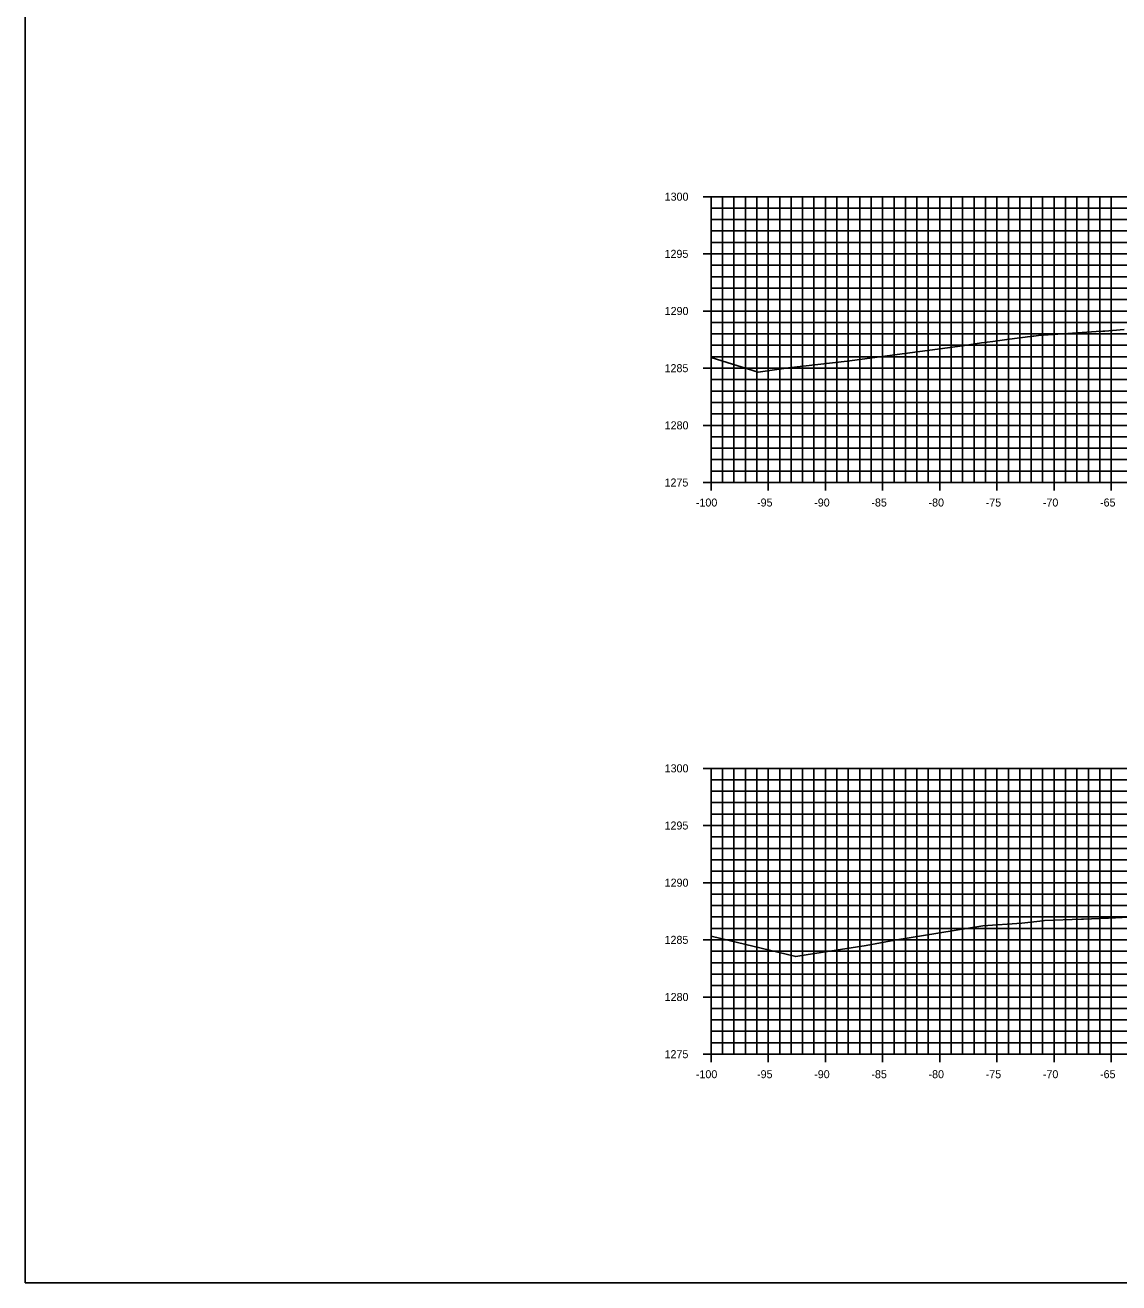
# Model space of a CAD drawing. Extents: x 674939 to 678919, y 750652 to 765176.
# Drawn here: x 677778.5 to 677874.2, y 757592.6 to 757702.6 of the extents above; entities that cross this region are included whole.
import ezdxf

# ---------------------------------------------------------------- set-up
doc = ezdxf.new("R2010")
doc.units = 0
for name, color, linetype in [('R_Axis', 7, 'Continuous'), ('R_Axis Annot', 7, 'Continuous'), ('R_Exist Surface', 7, 'Continuous'), ('R_Grid', 7, 'Continuous'), ('R_No Plot', 7, 'Continuous')]:
    doc.layers.add(name, color=color, linetype=linetype)

msp = doc.modelspace()

# ---------------------------------------------------------------- linework, layer by layer
at = {"layer": 'R_Axis'}
for p, q in [((677837.83, 757687.55), (677839.23, 757687.55)), ((677838.53, 757662.55), (677838.53, 757687.55)), ((677838.53, 757686.55), (677838.88, 757686.55)), ((677838.53, 757685.55), (677838.88, 757685.55)), ((677838.53, 757684.55), (677838.88, 757684.55)), ((677838.53, 757683.55), (677838.88, 757683.55)), ((677837.83, 757682.55), (677839.23, 757682.55)), ((677838.53, 757681.55), (677838.88, 757681.55)), ((677838.53, 757680.55), (677838.88, 757680.55)), ((677838.53, 757679.55), (677838.88, 757679.55)), ((677838.53, 757678.55), (677838.88, 757678.55)), ((677837.83, 757677.55), (677839.23, 757677.55)), ((677838.53, 757676.55), (677838.88, 757676.55)), ((677838.53, 757675.55), (677838.88, 757675.55)), ((677838.53, 757674.55), (677838.88, 757674.55)), ((677838.53, 757673.55), (677838.88, 757673.55)), ((677837.83, 757672.55), (677839.23, 757672.55)), ((677838.53, 757671.55), (677838.88, 757671.55)), ((677838.53, 757670.55), (677838.88, 757670.55)), ((677838.53, 757669.55), (677838.88, 757669.55)), ((677838.53, 757668.55), (677838.88, 757668.55)), ((677837.83, 757667.55), (677839.23, 757667.55)), ((677838.53, 757666.55), (677838.88, 757666.55)), ((677838.53, 757665.55), (677838.88, 757665.55)), ((677838.53, 757664.55), (677838.88, 757664.55)), ((677838.53, 757663.55), (677838.88, 757663.55)), ((677837.83, 757662.55), (677839.23, 757662.55)), ((677838.53, 757661.85), (677838.53, 757663.25)), ((677838.53, 757662.55), (678038.53, 757662.55)), ((677843.53, 757661.85), (677843.53, 757663.25)), ((677848.53, 757661.85), (677848.53, 757663.25)), ((677853.53, 757661.85), (677853.53, 757663.25)), ((677858.53, 757661.85), (677858.53, 757663.25)), ((677863.53, 757661.85), (677863.53, 757663.25)), ((677868.53, 757661.85), (677868.53, 757663.25)), ((677873.53, 757661.85), (677873.53, 757663.25)), ((677837.83, 757637.55), (677839.23, 757637.55)), ((677838.53, 757612.55), (677838.53, 757637.55)), ((677838.53, 757636.55), (677838.88, 757636.55)), ((677838.53, 757635.55), (677838.88, 757635.55)), ((677838.53, 757634.55), (677838.88, 757634.55)), ((677838.53, 757633.55), (677838.88, 757633.55)), ((677837.83, 757632.55), (677839.23, 757632.55)), ((677838.53, 757631.55), (677838.88, 757631.55)), ((677838.53, 757630.55), (677838.88, 757630.55)), ((677838.53, 757629.55), (677838.88, 757629.55)), ((677838.53, 757628.55), (677838.88, 757628.55)), ((677837.83, 757627.55), (677839.23, 757627.55)), ((677838.53, 757626.55), (677838.88, 757626.55)), ((677838.53, 757625.55), (677838.88, 757625.55)), ((677838.53, 757624.55), (677838.88, 757624.55)), ((677838.53, 757623.55), (677838.88, 757623.55)), ((677837.83, 757622.55), (677839.23, 757622.55)), ((677838.53, 757621.55), (677838.88, 757621.55)), ((677838.53, 757620.55), (677838.88, 757620.55)), ((677838.53, 757619.55), (677838.88, 757619.55)), ((677838.53, 757618.55), (677838.88, 757618.55)), ((677837.83, 757617.55), (677839.23, 757617.55)), ((677838.53, 757616.55), (677838.88, 757616.55)), ((677838.53, 757615.55), (677838.88, 757615.55)), ((677838.53, 757614.55), (677838.88, 757614.55)), ((677838.53, 757613.55), (677838.88, 757613.55)), ((677838.53, 757611.85), (677838.53, 757613.25)), ((677843.53, 757611.85), (677843.53, 757613.25)), ((677848.53, 757611.85), (677848.53, 757613.25)), ((677853.53, 757611.85), (677853.53, 757613.25)), ((677858.53, 757611.85), (677858.53, 757613.25)), ((677863.53, 757611.85), (677863.53, 757613.25)), ((677868.53, 757611.85), (677868.53, 757613.25)), ((677873.53, 757611.85), (677873.53, 757613.25)), ((677837.83, 757612.55), (677839.23, 757612.55)), ((677838.53, 757612.55), (678038.53, 757612.55))]:
    msp.add_line(p, q, dxfattribs=at)
at = {"layer": 'R_Exist Surface'}
for points in [[(677838.53, 757673.49), (677842.64, 757672.2), (677845.3, 757672.57), (677850.42, 757673.16), (677860.53, 757674.51), (677862.18, 757674.78), (677863.16, 757674.88), (677864.4, 757675.05), (677866.68, 757675.36), (677866.77, 757675.36), (677867.18, 757675.4), (677869.29, 757675.56), (677870.58, 757675.64), (677872.2, 757675.75), (677872.8, 757675.79), (677872.84, 757675.79), (677872.96, 757675.8), (677874.66, 757675.93)], [(677838.53, 757622.87), (677845.94, 757621.09), (677846.86, 757621.24), (677852.1, 757622.07), (677854.6, 757622.51), (677862.3, 757623.77), (677865.71, 757624), (677867.55, 757624.21), (677867.68, 757624.23), (677867.7, 757624.23), (677870.94, 757624.37), (677871.09, 757624.37), (677873.19, 757624.46), (677873.28, 757624.46), (677876.91, 757624.62)]]:
    msp.add_lwpolyline(points, dxfattribs=at)
at = {"layer": 'R_Grid'}
for p, q in [((677838.53, 757687.55), (678038.53, 757687.55)), ((677838.53, 757662.55), (677838.53, 757687.55)), ((677839.53, 757662.55), (677839.53, 757687.55)), ((677840.53, 757662.55), (677840.53, 757687.55)), ((677841.53, 757662.55), (677841.53, 757687.55)), ((677842.53, 757662.55), (677842.53, 757687.55)), ((677843.53, 757662.55), (677843.53, 757687.55)), ((677844.53, 757662.55), (677844.53, 757687.55)), ((677845.53, 757662.55), (677845.53, 757687.55)), ((677846.53, 757662.55), (677846.53, 757687.55)), ((677847.53, 757662.55), (677847.53, 757687.55)), ((677848.53, 757662.55), (677848.53, 757687.55)), ((677849.53, 757662.55), (677849.53, 757687.55)), ((677850.53, 757662.55), (677850.53, 757687.55)), ((677851.53, 757662.55), (677851.53, 757687.55)), ((677852.53, 757662.55), (677852.53, 757687.55)), ((677853.53, 757662.55), (677853.53, 757687.55)), ((677854.53, 757662.55), (677854.53, 757687.55)), ((677855.53, 757662.55), (677855.53, 757687.55)), ((677856.53, 757662.55), (677856.53, 757687.55)), ((677857.53, 757662.55), (677857.53, 757687.55)), ((677858.53, 757662.55), (677858.53, 757687.55)), ((677859.53, 757662.55), (677859.53, 757687.55)), ((677860.53, 757662.55), (677860.53, 757687.55)), ((677861.53, 757662.55), (677861.53, 757687.55)), ((677862.53, 757662.55), (677862.53, 757687.55)), ((677863.53, 757662.55), (677863.53, 757687.55)), ((677864.53, 757662.55), (677864.53, 757687.55)), ((677865.53, 757662.55), (677865.53, 757687.55)), ((677866.53, 757662.55), (677866.53, 757687.55)), ((677867.53, 757662.55), (677867.53, 757687.55)), ((677868.53, 757662.55), (677868.53, 757687.55)), ((677869.53, 757662.55), (677869.53, 757687.55)), ((677870.53, 757662.55), (677870.53, 757687.55)), ((677871.53, 757662.55), (677871.53, 757687.55)), ((677872.53, 757662.55), (677872.53, 757687.55)), ((677873.53, 757662.55), (677873.53, 757687.55)), ((677838.53, 757686.55), (678038.53, 757686.55)), ((677838.53, 757685.55), (678038.53, 757685.55)), ((677838.53, 757684.55), (678038.53, 757684.55)), ((677838.53, 757683.55), (678038.53, 757683.55)), ((677838.53, 757682.55), (678038.53, 757682.55)), ((677838.53, 757681.55), (678038.53, 757681.55)), ((677838.53, 757680.55), (678038.53, 757680.55)), ((677838.53, 757679.55), (678038.53, 757679.55)), ((677838.53, 757678.55), (678038.53, 757678.55)), ((677838.53, 757677.55), (678038.53, 757677.55)), ((677838.53, 757676.55), (678038.53, 757676.55)), ((677838.53, 757675.55), (678038.53, 757675.55)), ((677838.53, 757674.55), (678038.53, 757674.55)), ((677838.53, 757673.55), (678038.53, 757673.55)), ((677838.53, 757672.55), (678038.53, 757672.55)), ((677838.53, 757671.55), (678038.53, 757671.55)), ((677838.53, 757670.55), (678038.53, 757670.55)), ((677838.53, 757669.55), (678038.53, 757669.55)), ((677838.53, 757668.55), (678038.53, 757668.55)), ((677838.53, 757667.55), (678038.53, 757667.55)), ((677838.53, 757666.55), (678038.53, 757666.55)), ((677838.53, 757665.55), (678038.53, 757665.55)), ((677838.53, 757664.55), (678038.53, 757664.55)), ((677838.53, 757663.55), (678038.53, 757663.55)), ((677838.53, 757662.55), (678038.53, 757662.55)), ((677838.53, 757637.55), (678038.53, 757637.55)), ((677838.53, 757612.55), (677838.53, 757637.55)), ((677839.53, 757612.55), (677839.53, 757637.55)), ((677840.53, 757612.55), (677840.53, 757637.55)), ((677841.53, 757612.55), (677841.53, 757637.55)), ((677842.53, 757612.55), (677842.53, 757637.55)), ((677843.53, 757612.55), (677843.53, 757637.55)), ((677844.53, 757612.55), (677844.53, 757637.55)), ((677845.53, 757612.55), (677845.53, 757637.55)), ((677846.53, 757612.55), (677846.53, 757637.55)), ((677847.53, 757612.55), (677847.53, 757637.55)), ((677848.53, 757612.55), (677848.53, 757637.55)), ((677849.53, 757612.55), (677849.53, 757637.55)), ((677850.53, 757612.55), (677850.53, 757637.55)), ((677851.53, 757612.55), (677851.53, 757637.55)), ((677852.53, 757612.55), (677852.53, 757637.55)), ((677853.53, 757612.55), (677853.53, 757637.55)), ((677854.53, 757612.55), (677854.53, 757637.55)), ((677855.53, 757612.55), (677855.53, 757637.55)), ((677856.53, 757612.55), (677856.53, 757637.55)), ((677857.53, 757612.55), (677857.53, 757637.55)), ((677858.53, 757612.55), (677858.53, 757637.55)), ((677859.53, 757612.55), (677859.53, 757637.55)), ((677860.53, 757612.55), (677860.53, 757637.55)), ((677861.53, 757612.55), (677861.53, 757637.55)), ((677862.53, 757612.55), (677862.53, 757637.55)), ((677863.53, 757612.55), (677863.53, 757637.55)), ((677864.53, 757612.55), (677864.53, 757637.55)), ((677865.53, 757612.55), (677865.53, 757637.55)), ((677866.53, 757612.55), (677866.53, 757637.55)), ((677867.53, 757612.55), (677867.53, 757637.55)), ((677868.53, 757612.55), (677868.53, 757637.55)), ((677869.53, 757612.55), (677869.53, 757637.55)), ((677870.53, 757612.55), (677870.53, 757637.55)), ((677871.53, 757612.55), (677871.53, 757637.55)), ((677872.53, 757612.55), (677872.53, 757637.55)), ((677873.53, 757612.55), (677873.53, 757637.55)), ((677838.53, 757636.55), (678038.53, 757636.55)), ((677838.53, 757635.55), (678038.53, 757635.55)), ((677838.53, 757634.55), (678038.53, 757634.55)), ((677838.53, 757633.55), (678038.53, 757633.55)), ((677838.53, 757632.55), (678038.53, 757632.55)), ((677838.53, 757631.55), (678038.53, 757631.55)), ((677838.53, 757630.55), (678038.53, 757630.55)), ((677838.53, 757629.55), (678038.53, 757629.55)), ((677838.53, 757628.55), (678038.53, 757628.55)), ((677838.53, 757627.55), (678038.53, 757627.55)), ((677838.53, 757626.55), (678038.53, 757626.55)), ((677838.53, 757625.55), (678038.53, 757625.55)), ((677838.53, 757624.55), (678038.53, 757624.55)), ((677838.53, 757623.55), (678038.53, 757623.55)), ((677838.53, 757622.55), (678038.53, 757622.55)), ((677838.53, 757621.55), (678038.53, 757621.55)), ((677838.53, 757620.55), (678038.53, 757620.55)), ((677838.53, 757619.55), (678038.53, 757619.55)), ((677838.53, 757618.55), (678038.53, 757618.55)), ((677838.53, 757617.55), (678038.53, 757617.55)), ((677838.53, 757616.55), (678038.53, 757616.55)), ((677838.53, 757615.55), (678038.53, 757615.55)), ((677838.53, 757614.55), (678038.53, 757614.55)), ((677838.53, 757613.55), (678038.53, 757613.55)), ((677838.53, 757612.55), (678038.53, 757612.55))]:
    msp.add_line(p, q, dxfattribs=at)
at = {"layer": 'R_No Plot'}
msp.add_lwpolyline([(677778.53, 757592.55), (678118.53, 757592.55), (678118.53, 757812.55), (677778.53, 757812.55)], close=True, dxfattribs=at)

# ---------------------------------------------------------------- texts
at = {"layer": 'R_Axis Annot'}
for s, p in [('1300', (677834.47, 757687.2)), ('1295', (677834.46, 757682.2)), ('1290', (677834.47, 757677.2)), ('1285', (677834.46, 757672.2)), ('1280', (677834.47, 757667.2)), ('1275', (677834.46, 757662.2)), ('-100', (677837.2, 757660.45)), ('-95', (677842.55, 757660.45)), ('-90', (677847.55, 757660.45)), ('-85', (677852.55, 757660.45)), ('-80', (677857.55, 757660.45)), ('-75', (677862.55, 757660.45)), ('-70', (677867.55, 757660.45)), ('-65', (677872.55, 757660.45)), ('1300', (677834.47, 757637.2)), ('1295', (677834.46, 757632.2)), ('1290', (677834.47, 757627.2)), ('1285', (677834.46, 757622.2)), ('1280', (677834.47, 757617.2)), ('1275', (677834.46, 757612.2)), ('-100', (677837.2, 757610.45)), ('-95', (677842.55, 757610.45)), ('-90', (677847.55, 757610.45)), ('-85', (677852.55, 757610.45)), ('-80', (677857.55, 757610.45)), ('-75', (677862.55, 757610.45)), ('-70', (677867.55, 757610.45)), ('-65', (677872.55, 757610.45))]:
    msp.add_text(s, height=0.7, dxfattribs=at).set_placement(p)

doc.saveas('drawing.dxf')
